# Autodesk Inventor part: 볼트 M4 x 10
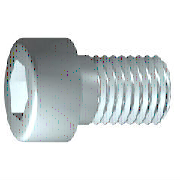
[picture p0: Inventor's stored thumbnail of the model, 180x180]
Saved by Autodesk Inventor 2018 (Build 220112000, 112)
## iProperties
IsCustomPart: 0
Created: 2016-04
Part Number: 볼트 M4 x 10
Material: 강철, 연강
Description: 6각머리 태핑 나사
Document SubType Name: Modeling
Standard: KS B 1003
Designer: mdu
Standards Organization: KS
Language: ko-KR
Size Designation: M 4 x 10
Categories: <MemberInstance><Categories><Category DisplayName="조임쇠" InternalName="e4da775c-781d-43d5-af7c-5136215cf5a6" Mnemonic="FSTN"><Category DisplayName="볼트" InternalN
Density: 7.86 g/cm^3
Mass: 2.0371 g
Surface Area: 3.0572 cm^2
Volume: 0.259174 cm^3
Appearance: 금속 1800F 열
Author: mdu
Revision Number: 1
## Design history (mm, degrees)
sketch "스케치1"
  geometry: L1 (-1, 0)-(10, 0); L2 (10, 0)-(10, 2); L3 (10, 2)-(1.75, 2); L4 (1.75, 2)-(1.32, 2); L5 (1.32, 2)-(0, 2); L6 (0, 2)-(0, 3.5); L7 (0, 3.5)-(-4, 3.5); L8 (-4, 3.5)-(-4, 1.732); L9 (-4, 1.732)-(-2, 1.732); L10 (-2, 1.732)-(-1, 0); L11 (-6.8, 0)-(12.8, 0) reference; L12 (0, -0.7)-(0, 4.2) reference; L13 (1.75, 2)-(0, 2)
  constraints: 22 end point, 6 parallel, 2 collinear, 2 perpendicular, 1 horizontal, 1 point on line
  dimensions: "d1" = 8.25 distance from line of L3.end L2 (= GEL); "d2" = 0.42952 distance of L4.end L3.end (computed from GAL); "d3" = 4 distance between parallel lines of L8 L6 (= KOH); "d4" = 2 distance of L8.end L9.end (= INTI); "d5" = 60 deg angle of L10 L1; "d6" = 4 diameter of L3 L1 (= GD); "d7" = 4 diameter of L5 L1 (= BDM); "d8" = 3.4641 diameter of L9 L1 (= 1.1547 x SW); "d9" = 7 diameter of L7 L1 (= KOD); "d26" = 10 distance between parallel lines of L12 L2 (= NLG)
revolve "본체" sketch "스케치1" stored, may be unused: angle "d10" = 90 deg
sketch "스케치2"
  geometry: L1 (0, -4.9)-(0, 4.9) reference; L2 (-4.9, 0)-(4.9, 0) reference; L3 (1.732, 0)-(0.866, -1.5); L4 (0.866, -1.5)-(-0.866, -1.5); L5 (-0.866, -1.5)-(-1.732, 0); L6 (-1.732, 0)-(-0.866, 1.5); L7 (-0.866, 1.5)-(0.866, 1.5); L8 (0.866, 1.5)-(1.732, 0); 2 further points
  constraints: 12 end point, 1 coincident, 1 horizontal alignment, 1 point on line, 12 other
extrude "슬롯" join sketch "스케치2" stored distance "d11" = 10; taper "d12" = 0 deg
workplane "Work Plane1"
fillet "Fillet2" dims "d30" = 0.1 (= R)
body "Solid1"
fillet "모깎기1" dims "d17" = 0.4 (= RR)
feature "스레드" dims "d13" = 8.25 (= GEL), "d14" = 0
chamfer "모따기1" distance "d15" = 0.42941 (= -0.5 x SPD + 0.5 x GD); stored, may be unused: second distance "d16" = 0.42941 (= GUL), angle "d27" = 45 deg
other parameters: "GD" = 4 (= NND) [user parameter; used in 2 equation terms], "NLG" = 10 [user parameter; used in 1 equation term], "GEL" = 8.25 [user parameter; used in 2 equation terms], "KOD" = 7 [user parameter; used in 1 equation term], "KOH" = 4 [user parameter; used in 1 equation term], "INTI" = 2 [user parameter; used in 1 equation term], "GAL" = 0.42941 (= 0.61345 x PTC) [user parameter; used in 1 equation term], "GUL" = 0.42941 (= 0.61345 x PTC) [user parameter; used in 1 equation term], "BDM" = 4 (= NND) [user parameter; used in 1 equation term], "SW" = 3 [user parameter; used in 2 equation terms], "RR" = 0.4 [user parameter; used in 1 equation term], "SPD" = 3.14117 (= NND - 1.2269 x PTC) [user parameter; used in 1 equation term], "d19" = 0, "d28" = 0, "d29" = 0, "R" = 0.1 [user parameter; used in 1 equation term], "PHH" = 0.2 [user parameter], "GD1" = 3.14117 (= THREADDIA - 1.2269 x PTC) [user parameter], "THREADDIA" = 4 [user parameter; used in 1 equation term], "FAWI" = 45 deg [user parameter], "TPU" = 14.28571 (computed from PTC) [user parameter], "PTC" = 0.7 [user parameter; used in 5 equation terms], "NND" = 4 [user parameter; used in 3 equation terms], "TOA" = 30 deg [user parameter], "E0" = 3.465 (= 1.155 x SW) [user parameter]
